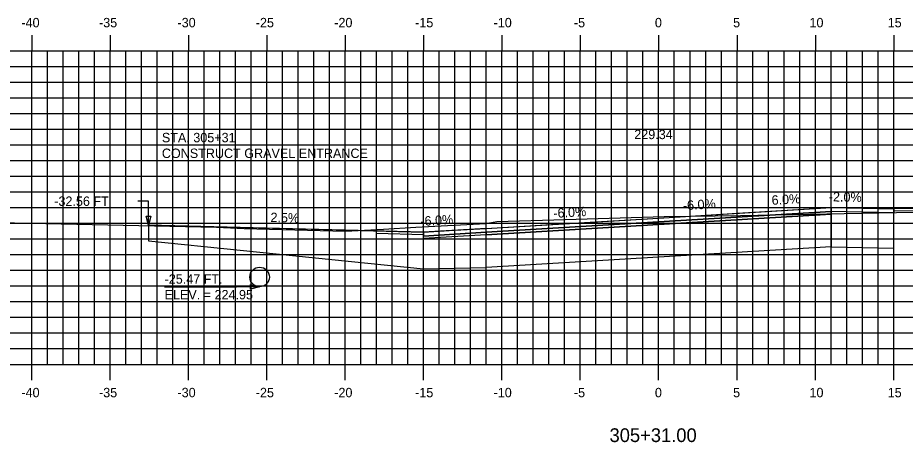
# Model space of a CAD drawing. Extents: x 1137211 to 1137381, y 608981 to 609091.
# Drawn here: x 1137253 to 1137309.6, y 609015.4 to 609042.4 of the extents above; entities that cross this region are included whole.
import ezdxf

# ---------------------------------------------------------------- set-up
doc = ezdxf.new("R2010")
doc.units = 0
for name, color, linetype in [('ANNOTATION', 7, 'Continuous'), ('D_Drainage_Culvert', 7, 'Continuous'), ('D_Roadway_Centerline', 7, 'Continuous'), ('D_Roadway_Centerline_Text', 7, 'Continuous'), ('D_Roadway_Edge_Shoulder', 7, 'Continuous'), ('D_Roadway_Edge_TW', 7, 'Continuous'), ('D_Roadway_Pavement', 7, 'Continuous'), ('D_Roadway_SubGrade', 7, 'Continuous'), ('D_Text_Standard', 7, 'Continuous'), ('H_V ANNOTATION', 7, 'Continuous'), ('MAJOR', 7, 'Continuous'), ('MINOR', 7, 'Continuous'), ('S_Roadway_Centerline', 7, 'Continuous')]:
    doc.layers.add(name, color=color, linetype=linetype)

msp = doc.modelspace()

# ---------------------------------------------------------------- linework, layer by layer
msp.add_lwpolyline([(1137261.336, 609029.209), (1137270.122, 609028.99), (1137278.896, 609028.77), (1137280.861, 609028.888), (1137282.896, 609029.01), (1137288.43, 609029.342), (1137293.896, 609029.67), (1137299.269, 609029.993), (1137304.896, 609030.33), (1137306.861, 609030.291), (1137308.896, 609030.25)])
at = {"layer": 'D_Drainage_Culvert'}
msp.add_circle((1137268.426, 609025.905), 0.625, dxfattribs=at)
at = {"layer": 'D_Roadway_Edge_Shoulder'}
for points in [[(1137304.896, 609030.33), (1137308.896, 609030.25), (1137308.896, 609030), (1137304.896, 609030.08)], [(1137327.036, 609030.192), (1137327.036, 609030.317), (1137308.896, 609030.25), (1137308.896, 609030.125)], [(1137278.896, 609028.77), (1137278.896, 609028.604), (1137275.897, 609028.679), (1137275.897, 609028.845)], [(1137282.896, 609029.01), (1137278.896, 609028.77), (1137278.896, 609028.52), (1137282.896, 609028.76)]]:
    msp.add_lwpolyline(points, close=True, dxfattribs=at)
at = {"layer": 'D_Roadway_Edge_TW'}
for points in [[(1137282.896, 609028.76), (1137282.896, 609029.01), (1137293.896, 609029.67), (1137304.896, 609030.33), (1137304.896, 609030.08), (1137293.896, 609029.42)], [(1137282.896, 609028.594), (1137278.896, 609028.354), (1137278.896, 609028.52), (1137282.896, 609028.76)]]:
    msp.add_lwpolyline(points, close=True, dxfattribs=at)
at = {"layer": 'D_Roadway_Pavement'}
msp.add_lwpolyline([(1137282.896, 609028.594), (1137282.896, 609028.76), (1137293.896, 609029.42), (1137304.896, 609030.08), (1137304.896, 609029.914), (1137293.896, 609029.254)], close=True, dxfattribs=at)
at = {"layer": 'D_Roadway_SubGrade'}
for points in [[(1137282.896, 609026.51), (1137282.896, 609028.594), (1137293.896, 609029.254), (1137304.896, 609029.914), (1137304.896, 609027.83), (1137293.896, 609027.17)], [(1137308.896, 609029.25), (1137308.896, 609030.25), (1137308.896, 609030.25), (1137308.896, 609030), (1137304.896, 609030.08), (1137304.896, 609029.914), (1137304.896, 609027.83), (1137308.896, 609027.75)], [(1137261.336, 609028.209), (1137278.896, 609026.43), (1137282.896, 609026.51), (1137282.896, 609028.594), (1137282.896, 609028.76), (1137278.896, 609028.52), (1137278.896, 609028.77), (1137261.336, 609029.209)]]:
    msp.add_lwpolyline(points, close=True, dxfattribs=at)
at = {"layer": 'D_Text_Standard'}
msp.add_line((1137262.361, 609025.28), (1137266.958, 609025.28), dxfattribs=at)
for points in [[(1137261.336, 609029.209), (1137261.327, 609030.743), (1137260.647, 609030.743)], [(1137268.426, 609025.28), (1137267.638, 609025.28), (1137266.958, 609025.28)]]:
    msp.add_lwpolyline(points, dxfattribs=at)
for points in [[(1137261.336, 609029.209), (1137261.187, 609029.791), (1137261.478, 609029.792)], [(1137268.426, 609025.28), (1137267.844, 609025.135), (1137267.844, 609025.426)]]:
    msp.add_lwpolyline(points, close=True, dxfattribs=at)
at = {"layer": 'MAJOR'}
for p, q in [((1137253.896, 609041.337), (1137253.896, 609040.335)), ((1137258.896, 609041.337), (1137258.896, 609040.335)), ((1137263.896, 609041.337), (1137263.896, 609040.335)), ((1137268.896, 609041.337), (1137268.896, 609040.335)), ((1137273.896, 609041.337), (1137273.896, 609040.335)), ((1137278.896, 609041.337), (1137278.896, 609040.335)), ((1137283.896, 609041.337), (1137283.896, 609040.335)), ((1137288.896, 609041.337), (1137288.896, 609040.335)), ((1137293.896, 609041.337), (1137293.896, 609040.335)), ((1137298.896, 609041.337), (1137298.896, 609040.335)), ((1137303.896, 609041.337), (1137303.896, 609040.335)), ((1137308.896, 609041.337), (1137308.896, 609040.335)), ((1137223.896, 609040.335), (1137363.896, 609040.335)), ((1137223.896, 609040.335), (1137363.896, 609040.335)), ((1137253.896, 609020.335), (1137253.896, 609040.335)), ((1137258.896, 609020.335), (1137258.896, 609040.335)), ((1137263.896, 609020.335), (1137263.896, 609040.335)), ((1137268.896, 609020.335), (1137268.896, 609040.335)), ((1137273.896, 609020.335), (1137273.896, 609040.335)), ((1137278.896, 609020.335), (1137278.896, 609040.335)), ((1137283.896, 609020.335), (1137283.896, 609040.335)), ((1137288.896, 609020.335), (1137288.896, 609040.335)), ((1137293.896, 609020.335), (1137293.896, 609040.335)), ((1137298.896, 609020.335), (1137298.896, 609040.335)), ((1137303.896, 609020.335), (1137303.896, 609040.335)), ((1137308.896, 609020.335), (1137308.896, 609040.335)), ((1137223.896, 609035.335), (1137363.896, 609035.335)), ((1137223.896, 609030.335), (1137363.896, 609030.335)), ((1137223.896, 609025.335), (1137363.896, 609025.335)), ((1137223.896, 609020.335), (1137363.896, 609020.335)), ((1137223.896, 609020.335), (1137363.896, 609020.335)), ((1137253.896, 609019.333), (1137253.896, 609020.335)), ((1137258.896, 609019.333), (1137258.896, 609020.335)), ((1137263.896, 609019.333), (1137263.896, 609020.335)), ((1137268.896, 609019.333), (1137268.896, 609020.335)), ((1137273.896, 609019.333), (1137273.896, 609020.335)), ((1137278.896, 609019.333), (1137278.896, 609020.335)), ((1137283.896, 609019.333), (1137283.896, 609020.335)), ((1137288.896, 609019.333), (1137288.896, 609020.335)), ((1137293.896, 609019.333), (1137293.896, 609020.335)), ((1137298.896, 609019.333), (1137298.896, 609020.335)), ((1137303.896, 609019.333), (1137303.896, 609020.335)), ((1137308.896, 609019.333), (1137308.896, 609020.335))]:
    msp.add_line(p, q, dxfattribs=at)
at = {"layer": 'MINOR'}
for p, q in [((1137254.896, 609020.335), (1137254.896, 609040.335)), ((1137255.896, 609020.335), (1137255.896, 609040.335)), ((1137256.896, 609020.335), (1137256.896, 609040.335)), ((1137257.896, 609020.335), (1137257.896, 609040.335)), ((1137259.896, 609020.335), (1137259.896, 609040.335)), ((1137260.896, 609020.335), (1137260.896, 609040.335)), ((1137261.896, 609020.335), (1137261.896, 609040.335)), ((1137262.896, 609020.335), (1137262.896, 609040.335)), ((1137264.896, 609020.335), (1137264.896, 609040.335)), ((1137265.896, 609020.335), (1137265.896, 609040.335)), ((1137266.896, 609020.335), (1137266.896, 609040.335)), ((1137267.896, 609020.335), (1137267.896, 609040.335)), ((1137269.896, 609020.335), (1137269.896, 609040.335)), ((1137270.896, 609020.335), (1137270.896, 609040.335)), ((1137271.896, 609020.335), (1137271.896, 609040.335)), ((1137272.896, 609020.335), (1137272.896, 609040.335)), ((1137274.896, 609020.335), (1137274.896, 609040.335)), ((1137275.896, 609020.335), (1137275.896, 609040.335)), ((1137276.896, 609020.335), (1137276.896, 609040.335)), ((1137277.896, 609020.335), (1137277.896, 609040.335)), ((1137279.896, 609020.335), (1137279.896, 609040.335)), ((1137280.896, 609020.335), (1137280.896, 609040.335)), ((1137281.896, 609020.335), (1137281.896, 609040.335)), ((1137282.896, 609020.335), (1137282.896, 609040.335)), ((1137284.896, 609020.335), (1137284.896, 609040.335)), ((1137285.896, 609020.335), (1137285.896, 609040.335)), ((1137286.896, 609020.335), (1137286.896, 609040.335)), ((1137287.896, 609020.335), (1137287.896, 609040.335)), ((1137289.896, 609020.335), (1137289.896, 609040.335)), ((1137290.896, 609020.335), (1137290.896, 609040.335)), ((1137291.896, 609020.335), (1137291.896, 609040.335)), ((1137292.896, 609020.335), (1137292.896, 609040.335)), ((1137294.896, 609020.335), (1137294.896, 609040.335)), ((1137295.896, 609020.335), (1137295.896, 609040.335)), ((1137296.896, 609020.335), (1137296.896, 609040.335)), ((1137297.896, 609020.335), (1137297.896, 609040.335)), ((1137299.896, 609020.335), (1137299.896, 609040.335)), ((1137300.896, 609020.335), (1137300.896, 609040.335)), ((1137301.896, 609020.335), (1137301.896, 609040.335)), ((1137302.896, 609020.335), (1137302.896, 609040.335)), ((1137304.896, 609020.335), (1137304.896, 609040.335)), ((1137305.896, 609020.335), (1137305.896, 609040.335)), ((1137306.896, 609020.335), (1137306.896, 609040.335)), ((1137307.896, 609020.335), (1137307.896, 609040.335)), ((1137223.896, 609039.335), (1137363.896, 609039.335)), ((1137223.896, 609038.335), (1137363.896, 609038.335)), ((1137223.896, 609037.335), (1137363.896, 609037.335)), ((1137223.896, 609036.335), (1137363.896, 609036.335)), ((1137223.896, 609034.335), (1137363.896, 609034.335)), ((1137223.896, 609033.335), (1137363.896, 609033.335)), ((1137223.896, 609032.335), (1137363.896, 609032.335)), ((1137223.896, 609031.335), (1137363.896, 609031.335)), ((1137223.896, 609029.335), (1137363.896, 609029.335)), ((1137223.896, 609028.335), (1137363.896, 609028.335)), ((1137223.896, 609027.335), (1137363.896, 609027.335)), ((1137223.896, 609026.335), (1137363.896, 609026.335)), ((1137223.896, 609024.335), (1137363.896, 609024.335)), ((1137223.896, 609023.335), (1137363.896, 609023.335)), ((1137223.896, 609022.335), (1137363.896, 609022.335)), ((1137223.896, 609021.335), (1137363.896, 609021.335))]:
    msp.add_line(p, q, dxfattribs=at)
at = {"layer": 'S_Roadway_Centerline'}
msp.add_lwpolyline([(1137223.896, 609030.475), (1137226.189, 609030.484), (1137228.443, 609030.476), (1137246.148, 609029.526), (1137248.798, 609029.444), (1137265.674, 609029.091), (1137267.433, 609029.009), (1137273.912, 609028.837), (1137276.343, 609028.953), (1137278.39, 609029.096), (1137282.861, 609029.317), (1137283.562, 609029.447), (1137287.936, 609029.577), (1137294.25, 609029.759), (1137299.127, 609029.829), (1137304.633, 609029.928), (1137312.395, 609030.077)], dxfattribs=at)

# ---------------------------------------------------------------- texts
at = {"layer": 'ANNOTATION'}
for s, p in [('STA. 305+31', (1137262.188, 609034.501)), ('CONSTRUCT GRAVEL ENTRANCE', (1137262.188, 609033.499))]:
    msp.add_text(s, height=0.6, dxfattribs=at).set_placement(p)
for s, rotation, p in [('6.0%', 3.4337, (1137301.121, 609030.506)), ('-2.0%', 358.8541, (1137304.751, 609030.733)), ('-6.0%', 3.4336, (1137287.193, 609029.67)), ('-6.0%', 3.4335, (1137295.46, 609030.166)), ('2.5%', 358.5679, (1137269.114, 609029.415)), ('-6.0%', 3.4335, (1137278.705, 609029.161))]:
    msp.add_text(s, height=0.6, rotation=rotation, dxfattribs=at).set_placement(p)
at = {"layer": 'D_Roadway_Centerline'}
for s, p in [('C', (1137293.891, 609029.67)), ('L', (1137293.896, 609029.663))]:
    msp.add_text(s, height=0.0146, dxfattribs=at).set_placement(p)
at = {"layer": 'D_Roadway_Centerline_Text'}
msp.add_text('229.34', height=0.6, dxfattribs=at).set_placement((1137292.339, 609034.702))
at = {"layer": 'D_Text_Standard'}
for s, p in [('-32.56 FT', (1137255.32, 609030.443)), ('-25.47 FT.', (1137262.361, 609025.48)), ('ELEV. = 224.95', (1137262.361, 609024.48))]:
    msp.add_text(s, height=0.6, dxfattribs=at).set_placement(p)
at = {"layer": 'H_V ANNOTATION'}
for s, height, p in [('-40', 0.6, (1137253.222, 609041.835)), ('-35', 0.6, (1137258.176, 609041.835)), ('-30', 0.6, (1137263.185, 609041.835)), ('-25', 0.6, (1137268.182, 609041.835)), ('-20', 0.6, (1137273.19, 609041.835)), ('-15', 0.6, (1137278.353, 609041.835)), ('-10', 0.6, (1137283.361, 609041.835)), ('-5', 0.6, (1137288.487, 609041.835)), ('0', 0.6, (1137293.655, 609041.835)), ('5', 0.6, (1137298.647, 609041.835)), ('10', 0.6, (1137303.522, 609041.835)), ('15', 0.6, (1137308.514, 609041.835)), ('-40', 0.6, (1137253.222, 609018.235)), ('-35', 0.6, (1137258.176, 609018.235)), ('-30', 0.6, (1137263.185, 609018.235)), ('-25', 0.6, (1137268.182, 609018.235)), ('-20', 0.6, (1137273.19, 609018.235)), ('-15', 0.6, (1137278.353, 609018.235)), ('-10', 0.6, (1137283.361, 609018.235)), ('-5', 0.6, (1137288.487, 609018.235)), ('0', 0.6, (1137293.655, 609018.235)), ('5', 0.6, (1137298.647, 609018.235)), ('10', 0.6, (1137303.522, 609018.235)), ('15', 0.6, (1137308.514, 609018.235)), ('305+31.00', 0.875, (1137290.76, 609015.378))]:
    msp.add_text(s, height=height, dxfattribs=at).set_placement(p)
at = {"layer": 'S_Roadway_Centerline'}
for s, p in [('C', (1137294.245, 609029.759)), ('L', (1137294.25, 609029.751))]:
    msp.add_text(s, height=0.0146, dxfattribs=at).set_placement(p)

doc.saveas('drawing.dxf')
